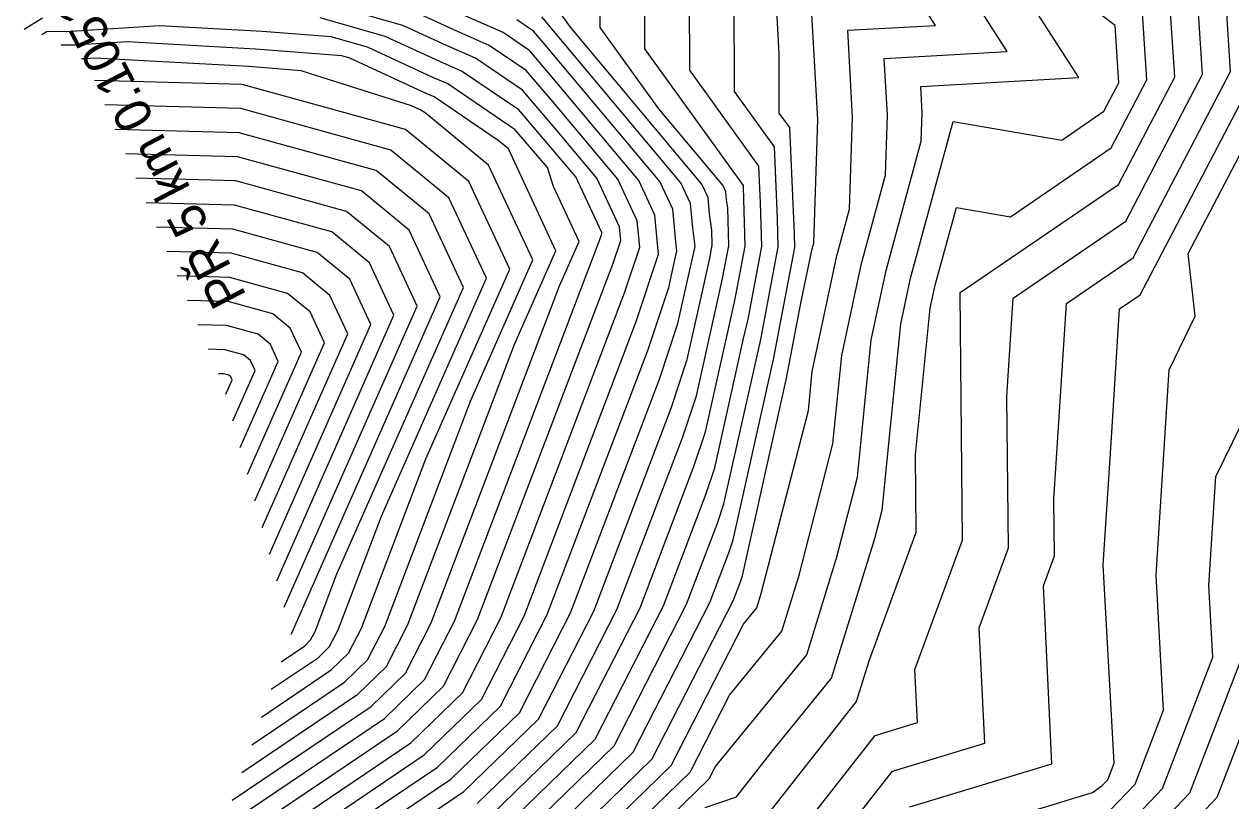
# Model space of a CAD drawing. Extents: x -549394 to -546608, y -1037055 to -1033629.
# Drawn here: x -547364 to -547062.1, y -1036469.1 to -1036274.8 of the extents above; entities that cross this region are included whole.
import ezdxf

# ---------------------------------------------------------------- set-up
doc = ezdxf.new("R2010")
doc.units = 0
for name, color, linetype in [('hlavni_vrst', 7, 'Continuous'), ('norm_vrst', 7, 'Continuous'), ('x_popis_pricne_rezy_C412', 7, 'Continuous')]:
    doc.layers.add(name, color=color, linetype=linetype)

msp = doc.modelspace()

# ---------------------------------------------------------------- linework, layer by layer
at = {"layer": 'hlavni_vrst'}
for p, q in [((-547069.17, -1036287.31), (-547074.04, -1036213.03)), ((-547118.07, -1036281.61), (-547155.85, -1036222.78)), ((-547197.5, -1036286.3), (-547197.57, -1036261.66)), ((-547236.58, -1036276.5), (-547240.76, -1036273.66)), ((-547358.25, -1036276.62), (-547359.58, -1036277.45)), ((-547353.55, -1036276.68), (-547358.25, -1036276.62)), ((-547330.13, -1036275.17), (-547353.55, -1036276.68)), ((-547304.5, -1036276.58), (-547330.13, -1036275.17)), ((-547287.25, -1036277.96), (-547304.5, -1036276.58)), ((-547233.65, -1036279.92), (-547236.58, -1036276.5)), ((-547278.11, -1036280.57), (-547287.25, -1036277.96)), ((-547205, -1036314.18), (-547233.65, -1036279.92)), ((-547261.73, -1036288.11), (-547278.11, -1036280.57)), ((-547148.84, -1036283.33), (-547118.07, -1036281.61)), ((-547148.05, -1036297.53), (-547148.84, -1036283.33)), ((-547180.18, -1036310.3), (-547197.5, -1036286.3)), ((-547258.02, -1036289.75), (-547261.73, -1036288.11)), ((-547088.4, -1036324.11), (-547069.17, -1036287.31)), ((-547241.17, -1036301.18), (-547258.02, -1036289.75)), ((-547148.53, -1036312.55), (-547148.05, -1036297.53)), ((-547310.24, -1036301.95), (-547341.25, -1036301.11)), ((-547233.04, -1036310.68), (-547241.17, -1036301.18)), ((-547275.97, -1036311.4), (-547310.24, -1036301.95)), ((-547231.58, -1036315.41), (-547233.04, -1036310.68)), ((-547179.79, -1036319.46), (-547180.18, -1036310.3)), ((-547262.71, -1036322.27), (-547275.97, -1036311.4)), ((-547154.52, -1036334.62), (-547148.53, -1036312.55)), ((-547225.17, -1036329.14), (-547231.58, -1036315.41)), ((-547201.75, -1036321.09), (-547205, -1036314.18)), ((-547179.47, -1036330.41), (-547179.79, -1036319.46)), ((-547254.12, -1036340.68), (-547262.71, -1036322.27)), ((-547200.98, -1036329.25), (-547201.75, -1036321.09)), ((-547116.55, -1036343.3), (-547088.4, -1036324.11)), ((-547312.21, -1036332.11), (-547328.31, -1036331.67)), ((-547230.08, -1036340.27), (-547225.17, -1036329.14)), ((-547201.63, -1036335.68), (-547200.69, -1036331.48)), ((-547200.69, -1036331.48), (-547200.98, -1036329.25)), ((-547182.91, -1036348.56), (-547179.47, -1036330.41)), ((-547294.41, -1036337.02), (-547312.21, -1036332.11)), ((-547159.44, -1036357.7), (-547154.52, -1036334.62)), ((-547287.53, -1036342.66), (-547294.41, -1036337.02)), ((-547202.75, -1036340.66), (-547201.63, -1036335.68)), ((-547285.76, -1036412.31), (-547254.12, -1036340.68)), ((-547262.19, -1036424.59), (-547230.08, -1036340.27)), ((-547207.98, -1036356.41), (-547202.75, -1036340.66)), ((-547283.06, -1036352.22), (-547287.53, -1036342.66)), ((-547118.12, -1036367.9), (-547116.55, -1036343.3)), ((-547184, -1036353.44), (-547182.91, -1036348.56)), ((-547304.48, -1036400.68), (-547283.06, -1036352.22)), ((-547191.24, -1036385.78), (-547184, -1036353.44)), ((-547233.13, -1036422.47), (-547207.98, -1036356.41)), ((-547161.66, -1036379.77), (-547159.44, -1036357.7)), ((-547314.17, -1036362.27), (-547315.37, -1036362.23)), ((-547312.85, -1036362.63), (-547314.17, -1036362.27)), ((-547313.6, -1036367.35), (-547312.01, -1036363.76)), ((-547312.34, -1036363.05), (-547312.85, -1036362.63)), ((-547312.01, -1036363.76), (-547312.34, -1036363.05)), ((-547117.75, -1036405.84), (-547118.12, -1036367.9)), ((-547170.12, -1036412.65), (-547161.66, -1036379.77)), ((-547193.45, -1036392.43), (-547191.24, -1036385.78)), ((-547204.08, -1036420.35), (-547193.45, -1036392.43)), ((-547125.06, -1036425.78), (-547117.75, -1036405.84)), ((-547291.24, -1036426.71), (-547285.76, -1036412.31)), ((-547174.46, -1036426.66), (-547170.12, -1036412.65)), ((-547221.12, -1036453.65), (-547204.08, -1036420.35)), ((-547072.34, -1036467.12), (-547054.25, -1036419.9)), ((-547268.6, -1036437.12), (-547262.19, -1036424.59)), ((-547244.86, -1036445.38), (-547233.13, -1036422.47)), ((-547292.34, -1036428.85), (-547291.24, -1036426.71)), ((-547187.53, -1036442.68), (-547174.46, -1036426.66)), ((-547123.69, -1036454.69), (-547125.06, -1036425.78)), ((-547299.75, -1036434.28), (-547293.81, -1036430.28)), ((-547293.81, -1036430.28), (-547292.34, -1036428.85)), ((-547277.21, -1036445.47), (-547268.6, -1036437.12)), ((-547197.38, -1036461.91), (-547187.53, -1036442.68)), ((-547311.97, -1036468.9), (-547277.21, -1036445.47)), ((-547260.62, -1036460.67), (-547244.86, -1036445.38)), ((-547244.02, -1036475.86), (-547221.12, -1036453.65)), ((-547146.77, -1036461.68), (-547123.69, -1036454.69)), ((-547324.2, -1036503.52), (-547260.62, -1036460.67)), ((-547227.42, -1036491.06), (-547197.38, -1036461.91)), ((-547164, -1036483.69), (-547146.77, -1036461.68)), ((-547088.34, -1036483.8), (-547072.34, -1036467.12))]:
    msp.add_line(p, q, dxfattribs=at)
at = {"layer": 'norm_vrst'}
for p, q in [((-547062.18, -1036286.6), (-547068.37, -1036192.34)), ((-547100.17, -1036288.14), (-547148.72, -1036212.54)), ((-547135.97, -1036275.08), (-547162.98, -1036233.01)), ((-547076.15, -1036288.03), (-547079.72, -1036233.71)), ((-547083.14, -1036288.74), (-547085.4, -1036254.39)), ((-547186.29, -1036291.65), (-547186.37, -1036259.67)), ((-547175.12, -1036282.28), (-547176.23, -1036262.27)), ((-547208.71, -1036280.94), (-547208.76, -1036263.66)), ((-547219.92, -1036275.58), (-547219.95, -1036265.66)), ((-547269.27, -1036275.09), (-547292.58, -1036268.45)), ((-547227.33, -1036275.5), (-547231.14, -1036270.23)), ((-547165.47, -1036298.6), (-547167.1, -1036269.29)), ((-547091.07, -1036275.08), (-547098.31, -1036269.7)), ((-547359.45, -1036273.24), (-547364.03, -1036276.1)), ((-547273.69, -1036277.83), (-547289.92, -1036273.21)), ((-547256.71, -1036276.1), (-547264.85, -1036272.35)), ((-547244.21, -1036276.88), (-547255.04, -1036272.1)), ((-547199.74, -1036314.48), (-547234.51, -1036272.91)), ((-547258.38, -1036280.1), (-547269.27, -1036275.09)), ((-547247.66, -1036280.09), (-547256.71, -1036276.1)), ((-547237.49, -1036281.43), (-547244.21, -1036276.88)), ((-547194.49, -1036314.77), (-547227.33, -1036275.5)), ((-547205.23, -1036295.94), (-547219.92, -1036275.58)), ((-547157.97, -1036276.31), (-547135.97, -1036275.08)), ((-547156.76, -1036298.06), (-547157.97, -1036276.31)), ((-547090.13, -1036289.46), (-547091.07, -1036275.08)), ((-547351.25, -1036280.07), (-547354.75, -1036280.02)), ((-547338.24, -1036279.23), (-547351.25, -1036280.07)), ((-547306.17, -1036281), (-547338.24, -1036279.23)), ((-547260.06, -1036284.11), (-547273.69, -1036277.83)), ((-547251.11, -1036283.31), (-547258.38, -1036280.1)), ((-547238.41, -1036286.37), (-547247.66, -1036280.09)), ((-547348.95, -1036283.45), (-547349.65, -1036283.44)), ((-547346.34, -1036283.29), (-547348.95, -1036283.45)), ((-547307.84, -1036285.41), (-547346.34, -1036283.29)), ((-547284.58, -1036282.72), (-547306.17, -1036281)), ((-547282.53, -1036283.31), (-547284.58, -1036282.72)), ((-547263.4, -1036292.12), (-547282.53, -1036283.31)), ((-547239.33, -1036291.31), (-547251.11, -1036283.31)), ((-547232.8, -1036286.93), (-547237.49, -1036281.43)), ((-547184.05, -1036315.11), (-547208.71, -1036280.94)), ((-547175.08, -1036297.01), (-547175.12, -1036282.28)), ((-547294.71, -1036286.46), (-547307.84, -1036285.41)), ((-547267.08, -1036295.19), (-547294.71, -1036286.46)), ((-547254.57, -1036286.53), (-547260.06, -1036284.11)), ((-547240.25, -1036296.24), (-547254.57, -1036286.53)), ((-547231.95, -1036293.93), (-547238.41, -1036286.37)), ((-547084.77, -1036342.46), (-547055.19, -1036285.88)), ((-547072.77, -1036332.15), (-547048.21, -1036285.17)), ((-547309.46, -1036289.88), (-547346.43, -1036288.88)), ((-547210.26, -1036313.88), (-547232.8, -1036286.93)), ((-547139.71, -1036290.34), (-547100.17, -1036288.14)), ((-547093.85, -1036296.58), (-547090.13, -1036289.46)), ((-547092.04, -1036305.75), (-547083.14, -1036288.74)), ((-547090.22, -1036314.93), (-547076.15, -1036288.03)), ((-547086.58, -1036333.28), (-547062.18, -1036286.6)), ((-547268.59, -1036301.15), (-547309.46, -1036289.88)), ((-547261.47, -1036292.96), (-547263.4, -1036292.12)), ((-547231.09, -1036300.94), (-547239.33, -1036291.31)), ((-547176.3, -1036305.48), (-547186.29, -1036291.65)), ((-547139.34, -1036296.99), (-547139.71, -1036290.34)), ((-547309.85, -1036295.91), (-547343.84, -1036295)), ((-547265.07, -1036296.12), (-547267.08, -1036295.19)), ((-547245.39, -1036303.87), (-547261.47, -1036292.96)), ((-547215.51, -1036313.59), (-547231.95, -1036293.93)), ((-547272.28, -1036306.28), (-547309.85, -1036295.91)), ((-547264.92, -1036296.18), (-547265.07, -1036296.12)), ((-547263.73, -1036296.99), (-547264.92, -1036296.18)), ((-547247.82, -1036310.03), (-547263.73, -1036296.99)), ((-547230.24, -1036307.95), (-547240.25, -1036296.24)), ((-547189.23, -1036315.07), (-547205.23, -1036295.94)), ((-547172.43, -1036300.67), (-547175.08, -1036297.01)), ((-547166.45, -1036329.6), (-547165.47, -1036298.6)), ((-547157.49, -1036321.08), (-547156.76, -1036298.06)), ((-547139.57, -1036304.02), (-547139.34, -1036296.99)), ((-547104.41, -1036303.78), (-547093.85, -1036296.58)), ((-547252.78, -1036314.11), (-547268.59, -1036301.15)), ((-547220.77, -1036313.29), (-547231.09, -1036300.94)), ((-547171.31, -1036327.3), (-547172.43, -1036300.67)), ((-547142.23, -1036338.29), (-547131.58, -1036299.1)), ((-547131.58, -1036299.1), (-547104.41, -1036303.78)), ((-547242.85, -1036305.95), (-547245.39, -1036303.87)), ((-547148.37, -1036336.45), (-547139.57, -1036304.02)), ((-547310.63, -1036307.98), (-547338.66, -1036307.22)), ((-547257.74, -1036318.19), (-547272.28, -1036306.28)), ((-547230.96, -1036331.45), (-547242.85, -1036305.95)), ((-547175.55, -1036323.38), (-547176.3, -1036305.48)), ((-547117.27, -1036322.95), (-547092.04, -1036305.75)), ((-547279.66, -1036316.52), (-547310.63, -1036307.98)), ((-547236.75, -1036333.76), (-547247.82, -1036310.03)), ((-547226.02, -1036312.99), (-547230.24, -1036307.95)), ((-547311.03, -1036314.01), (-547336.07, -1036313.33)), ((-547219.49, -1036326.9), (-547226.02, -1036312.99)), ((-547215.05, -1036325.45), (-547220.77, -1036313.29)), ((-547210.62, -1036324), (-547215.51, -1036313.59)), ((-547283.35, -1036321.65), (-547311.03, -1036314.01)), ((-547267.67, -1036326.35), (-547279.66, -1036316.52)), ((-547242.54, -1036336.07), (-547252.78, -1036314.11)), ((-547206.19, -1036322.54), (-547210.26, -1036313.88)), ((-547197.32, -1036319.64), (-547199.74, -1036314.48)), ((-547192.89, -1036318.18), (-547194.49, -1036314.77)), ((-547188.45, -1036316.73), (-547189.23, -1036315.07)), ((-547188.27, -1036318.69), (-547188.45, -1036316.73)), ((-547184.03, -1036315.55), (-547184.05, -1036315.11)), ((-547183.6, -1036330.31), (-547184.03, -1036315.55)), ((-547129.86, -1036341.95), (-547090.22, -1036314.93)), ((-547311.42, -1036320.04), (-547333.49, -1036319.45)), ((-547248.33, -1036338.37), (-547257.74, -1036318.19)), ((-547196.74, -1036325.73), (-547197.32, -1036319.64)), ((-547192.51, -1036322.21), (-547192.89, -1036318.18)), ((-547188, -1036320.71), (-547188.27, -1036318.69)), ((-547287.04, -1036326.77), (-547311.42, -1036320.04)), ((-547272.64, -1036330.42), (-547283.35, -1036321.65)), ((-547205.27, -1036332.3), (-547206.19, -1036322.54)), ((-547191.97, -1036326.36), (-547192.51, -1036322.21)), ((-547187.73, -1036330.2), (-547188, -1036320.71)), ((-547160.67, -1036332.78), (-547157.49, -1036321.08)), ((-547136.08, -1036340.12), (-547130.78, -1036320.63)), ((-547130.78, -1036320.63), (-547117.27, -1036322.95)), ((-547311.81, -1036326.07), (-547330.9, -1036325.56)), ((-547214.73, -1036328.87), (-547215.05, -1036325.45)), ((-547210, -1036330.58), (-547210.62, -1036324)), ((-547196.14, -1036330.4), (-547196.74, -1036325.73)), ((-547175.34, -1036330.51), (-547175.55, -1036323.38)), ((-547290.72, -1036331.89), (-547311.81, -1036326.07)), ((-547277.6, -1036334.5), (-547287.04, -1036326.77)), ((-547259.91, -1036342.99), (-547267.67, -1036326.35)), ((-547256.38, -1036424.17), (-547219.61, -1036327.6)), ((-547219.61, -1036327.6), (-547219.46, -1036327.16)), ((-547219.46, -1036327.16), (-547219.49, -1036326.9)), ((-547191.86, -1036330.1), (-547191.97, -1036326.36)), ((-547171.21, -1036330.62), (-547171.31, -1036327.3)), ((-547265.7, -1036345.3), (-547272.64, -1036330.42)), ((-547241.22, -1036354.68), (-547230.96, -1036331.45)), ((-547216.7, -1036334.8), (-547214.73, -1036328.87)), ((-547213.79, -1036342), (-547210, -1036330.58)), ((-547198.11, -1036339.23), (-547196.14, -1036330.4)), ((-547192.47, -1036333.33), (-547191.86, -1036330.1)), ((-547189.28, -1036338.41), (-547187.73, -1036330.2)), ((-547186.1, -1036343.49), (-547183.6, -1036330.31)), ((-547179.73, -1036353.64), (-547175.34, -1036330.51)), ((-547176.54, -1036358.72), (-547171.21, -1036330.62)), ((-547169.63, -1036344.14), (-547166.82, -1036330.95)), ((-547166.82, -1036330.95), (-547166.45, -1036329.6)), ((-547282.56, -1036338.58), (-547290.72, -1036331.89)), ((-547271.49, -1036347.6), (-547277.6, -1036334.5)), ((-547252.35, -1036369.09), (-547236.75, -1036333.76)), ((-547250.57, -1036423.74), (-547216.7, -1036334.8)), ((-547210.89, -1036349.21), (-547205.27, -1036332.3)), ((-547194.58, -1036342.79), (-547192.47, -1036333.33)), ((-547166.82, -1036361.65), (-547160.67, -1036332.78)), ((-547103.24, -1036344.64), (-547086.58, -1036333.28)), ((-547071, -1036347.87), (-547072.77, -1036332.15)), ((-547312.6, -1036338.14), (-547325.72, -1036337.78)), ((-547263.49, -1036383.5), (-547242.54, -1036336.07)), ((-547152.06, -1036353.75), (-547148.37, -1036336.45)), ((-547298.1, -1036342.14), (-547312.6, -1036338.14)), ((-547277.28, -1036349.91), (-547282.56, -1036338.58)), ((-547274.63, -1036397.9), (-547248.33, -1036338.37)), ((-547200.44, -1036349.68), (-547198.11, -1036339.23)), ((-547191.05, -1036346.34), (-547189.28, -1036338.41)), ((-547144.68, -1036349.8), (-547142.23, -1036338.29)), ((-547137.3, -1036345.85), (-547136.08, -1036340.12)), ((-547312.99, -1036344.17), (-547323.13, -1036343.9)), ((-547292.49, -1036346.74), (-547298.1, -1036342.14)), ((-547296.9, -1036426.72), (-547259.91, -1036342.99)), ((-547244.76, -1036423.32), (-547213.79, -1036342)), ((-547198.14, -1036358.71), (-547194.58, -1036342.79)), ((-547187.53, -1036349.89), (-547186.1, -1036343.49)), ((-547129.87, -1036342.2), (-547129.86, -1036341.95)), ((-547129.27, -1036403.85), (-547129.87, -1036342.2)), ((-547089.94, -1036345.99), (-547084.77, -1036342.46)), ((-547301.79, -1036347.26), (-547312.99, -1036344.17)), ((-547299, -1036420.68), (-547265.7, -1036345.3)), ((-547288.85, -1036354.53), (-547292.49, -1036346.74)), ((-547195.84, -1036367.73), (-547191.05, -1036346.34)), ((-547173.36, -1036363.79), (-547169.63, -1036344.14)), ((-547140.98, -1036382.52), (-547137.3, -1036345.85)), ((-547106.37, -1036393.61), (-547103.24, -1036344.64)), ((-547092.09, -1036379.65), (-547089.94, -1036345.99)), ((-547302.65, -1036407.35), (-547277.28, -1036349.91)), ((-547297.45, -1036350.81), (-547301.79, -1036347.26)), ((-547300.83, -1036414.02), (-547271.49, -1036347.6)), ((-547238.94, -1036422.9), (-547210.89, -1036349.21)), ((-547205.07, -1036363.62), (-547200.44, -1036349.68)), ((-547193.54, -1036376.75), (-547187.53, -1036349.89)), ((-547149.36, -1036396.39), (-547144.68, -1036349.8)), ((-547077.52, -1036361.28), (-547071, -1036347.87)), ((-547313.39, -1036350.2), (-547320.54, -1036350.01)), ((-547305.48, -1036352.38), (-547313.39, -1036350.2)), ((-547302.42, -1036354.89), (-547305.48, -1036352.38)), ((-547294.64, -1036356.83), (-547297.45, -1036350.81)), ((-547065.84, -1036387.99), (-547047.46, -1036350.21)), ((-547306.3, -1036394.01), (-547288.85, -1036354.53)), ((-547300.43, -1036359.14), (-547302.42, -1036354.89)), ((-547268, -1036425.02), (-547241.22, -1036354.68)), ((-547180.48, -1036357), (-547179.73, -1036353.64)), ((-547155.51, -1036388.08), (-547152.06, -1036353.75)), ((-547313.78, -1036356.23), (-547317.95, -1036356.12)), ((-547309.17, -1036357.51), (-547313.78, -1036356.23)), ((-547307.38, -1036358.97), (-547309.17, -1036357.51)), ((-547308.13, -1036387.35), (-547294.64, -1036356.83)), ((-547306.22, -1036361.45), (-547307.38, -1036358.97)), ((-547202.17, -1036370.82), (-547198.14, -1036358.71)), ((-547188.93, -1036394.8), (-547180.48, -1036357)), ((-547176.95, -1036360.55), (-547176.54, -1036358.72)), ((-547311.78, -1036374.01), (-547306.22, -1036361.45)), ((-547309.95, -1036380.68), (-547300.43, -1036359.14)), ((-547186.63, -1036403.82), (-547176.95, -1036360.55)), ((-547167.8, -1036371.46), (-547166.82, -1036361.65)), ((-547080.81, -1036412.66), (-547077.52, -1036361.28)), ((-547227.32, -1036422.05), (-547205.07, -1036363.62)), ((-547184.33, -1036412.84), (-547173.43, -1036364.1)), ((-547173.43, -1036364.1), (-547173.36, -1036363.79)), ((-547199.26, -1036378.02), (-547195.84, -1036367.73)), ((-547273.81, -1036425.44), (-547252.35, -1036369.09)), ((-547221.51, -1036421.62), (-547202.17, -1036370.82)), ((-547179.59, -1036417.24), (-547167.8, -1036371.46)), ((-547196.35, -1036385.23), (-547193.54, -1036376.75)), ((-547215.7, -1036421.2), (-547199.26, -1036378.02)), ((-547094.03, -1036410.07), (-547092.09, -1036379.65)), ((-547140.8, -1036401.86), (-547140.98, -1036382.52)), ((-547279.62, -1036425.87), (-547263.49, -1036383.5)), ((-547209.89, -1036420.78), (-547196.35, -1036385.23)), ((-547160.66, -1036408.07), (-547155.51, -1036388.08)), ((-547067.58, -1036415.25), (-547065.84, -1036387.99)), ((-547190.54, -1036399.64), (-547188.93, -1036394.8)), ((-547106.23, -1036407.83), (-547106.37, -1036393.61)), ((-547285.43, -1036426.29), (-547274.63, -1036397.9)), ((-547151.19, -1036403.48), (-547149.36, -1036396.39)), ((-547198.27, -1036419.93), (-547190.54, -1036399.64)), ((-547187.63, -1036406.84), (-547186.63, -1036403.82)), ((-547161.99, -1036438.4), (-547151.19, -1036403.48)), ((-547152.61, -1036434.1), (-547140.8, -1036401.86)), ((-547141.15, -1036436.25), (-547129.27, -1036403.85)), ((-547192.46, -1036419.5), (-547187.63, -1036406.84)), ((-547168.22, -1036432.53), (-547160.66, -1036408.07)), ((-547108.97, -1036415.31), (-547106.23, -1036407.83)), ((-547091.33, -1036459.67), (-547094.03, -1036410.07)), ((-547184.73, -1036414.05), (-547184.33, -1036412.84)), ((-547078.97, -1036446.41), (-547080.81, -1036412.66)), ((-547186.65, -1036419.08), (-547184.73, -1036414.05)), ((-547106.86, -1036459.85), (-547108.97, -1036415.31)), ((-547066.61, -1036433.16), (-547067.58, -1036415.25)), ((-547206.88, -1036458.61), (-547186.65, -1036419.08)), ((-547180.69, -1036420.8), (-547179.59, -1036417.24)), ((-547240.11, -1036447.04), (-547227.32, -1036422.05)), ((-547235.36, -1036448.69), (-547221.51, -1036421.62)), ((-547230.62, -1036450.34), (-547215.7, -1036421.2)), ((-547225.87, -1036451.99), (-547209.89, -1036420.78)), ((-547216.37, -1036455.3), (-547198.27, -1036419.93)), ((-547211.62, -1036456.95), (-547192.46, -1036419.5)), ((-547184.01, -1036424.86), (-547180.69, -1036420.8)), ((-547278.1, -1036433.81), (-547273.81, -1036425.44)), ((-547273.35, -1036435.46), (-547268, -1036425.02)), ((-547263.85, -1036438.77), (-547256.38, -1036424.17)), ((-547259.1, -1036440.42), (-547250.57, -1036423.74)), ((-547254.36, -1036442.08), (-547244.76, -1036423.32)), ((-547249.61, -1036443.73), (-547238.94, -1036422.9)), ((-547202.13, -1036460.26), (-547184.01, -1036424.86)), ((-547297.3, -1036427.36), (-547297.13, -1036427.24)), ((-547297.13, -1036427.24), (-547297.09, -1036427.2)), ((-547297.09, -1036427.2), (-547297.06, -1036427.14)), ((-547297.06, -1036427.14), (-547296.9, -1036426.72)), ((-547287.59, -1036430.51), (-547285.43, -1036426.29)), ((-547282.84, -1036432.16), (-547279.62, -1036425.87)), ((-547290.49, -1036433.32), (-547287.59, -1036430.51)), ((-547302.19, -1036441.2), (-547290.49, -1036433.32)), ((-547287.17, -1036436.36), (-547282.84, -1036432.16)), ((-547283.85, -1036439.4), (-547278.1, -1036433.81)), ((-547191.06, -1036460.49), (-547168.22, -1036432.53)), ((-547155.76, -1036444.27), (-547152.61, -1036434.1)), ((-547079.2, -1036466.02), (-547066.61, -1036433.16)), ((-547065.49, -1036468.22), (-547052.36, -1036433.96)), ((-547304.64, -1036448.13), (-547287.17, -1036436.36)), ((-547280.53, -1036442.44), (-547273.35, -1036435.46)), ((-547140.52, -1036449.53), (-547141.15, -1036436.25)), ((-547307.08, -1036455.05), (-547283.85, -1036439.4)), ((-547273.89, -1036448.51), (-547263.85, -1036438.77)), ((-547270.57, -1036451.55), (-547259.1, -1036440.42)), ((-547176.48, -1036456.14), (-547161.99, -1036438.4)), ((-547309.53, -1036461.98), (-547280.53, -1036442.44)), ((-547267.25, -1036454.59), (-547254.36, -1036442.08)), ((-547263.93, -1036457.63), (-547249.61, -1036443.73)), ((-547157.64, -1036446.58), (-547155.76, -1036444.27)), ((-547086.06, -1036464.92), (-547078.97, -1036446.41)), ((-547314.42, -1036475.82), (-547273.89, -1036448.51)), ((-547257.3, -1036463.71), (-547240.11, -1036447.04)), ((-547253.98, -1036466.75), (-547235.36, -1036448.69)), ((-547178.55, -1036473.29), (-547157.64, -1036446.58)), ((-547151.12, -1036452.75), (-547140.52, -1036449.53)), ((-547316.86, -1036482.75), (-547270.57, -1036451.55)), ((-547250.66, -1036469.78), (-547230.62, -1036450.34)), ((-547247.34, -1036472.82), (-547225.87, -1036451.99)), ((-547319.31, -1036489.67), (-547267.25, -1036454.59)), ((-547240.7, -1036478.9), (-547216.37, -1036455.3)), ((-547171.27, -1036478.49), (-547151.12, -1036452.75)), ((-547321.76, -1036496.59), (-547263.93, -1036457.63)), ((-547237.38, -1036481.94), (-547211.62, -1036456.95)), ((-547234.06, -1036484.98), (-547206.88, -1036458.61)), ((-547185.83, -1036468.09), (-547176.48, -1036456.14)), ((-547230.74, -1036488.02), (-547202.13, -1036460.26)), ((-547192.63, -1036463.57), (-547191.06, -1036460.49)), ((-547142.41, -1036470.62), (-547106.86, -1036459.85)), ((-547092.92, -1036463.83), (-547091.33, -1036459.67)), ((-547326.65, -1036510.44), (-547257.3, -1036463.71)), ((-547224.1, -1036494.1), (-547192.63, -1036463.57)), ((-547094.33, -1036465.3), (-547092.92, -1036463.83)), ((-547329.09, -1036517.36), (-547253.98, -1036466.75)), ((-547138.06, -1036479.55), (-547096.73, -1036467.03)), ((-547096.73, -1036467.03), (-547094.33, -1036465.3)), ((-547092.33, -1036471.47), (-547086.06, -1036464.92)), ((-547090.34, -1036477.64), (-547079.2, -1036466.02)), ((-547193.63, -1036470.8), (-547185.83, -1036468.09)), ((-547086.34, -1036489.97), (-547065.49, -1036468.22))]:
    msp.add_line(p, q, dxfattribs=at)

# ---------------------------------------------------------------- texts
at = {"layer": 'x_popis_pricne_rezy_C412'}
msp.add_text('PŘ 5 km 0.1051', height=9.0627, rotation=117.4888, dxfattribs=at).set_placement((-547308.28, -1036342.72))

doc.saveas('drawing.dxf')
